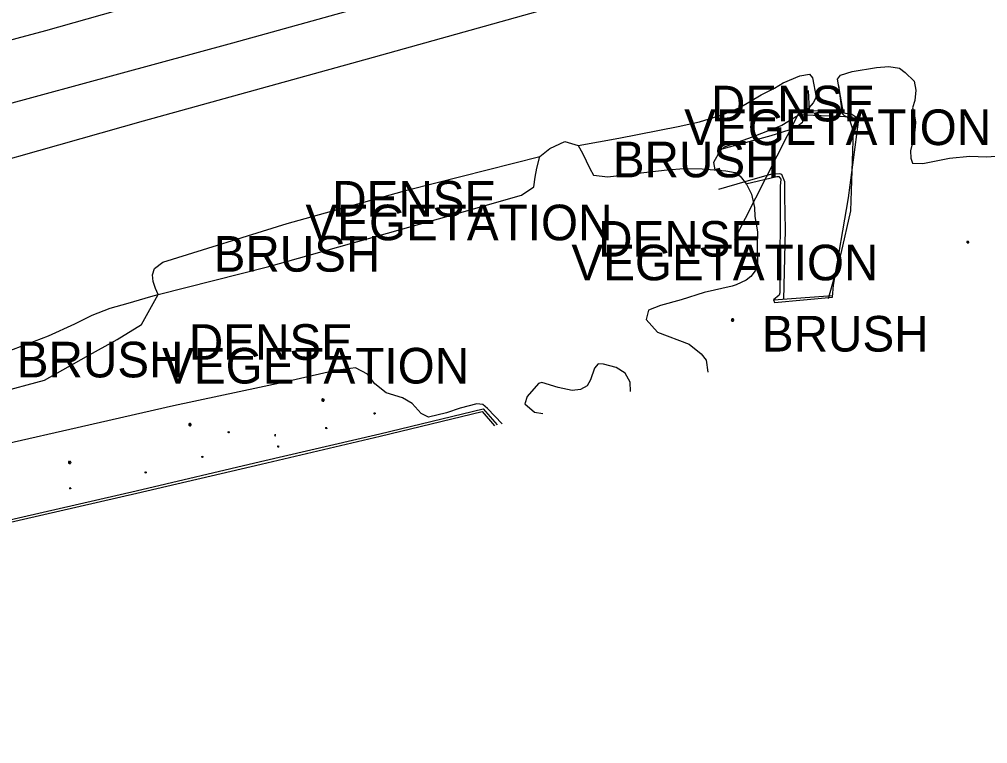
# Model space of a CAD drawing. Extents: x 2129547 to 2134906, y 657330 to 659734.
# Drawn here: x 2130043 to 2130233.3, y 657679.1 to 657821.5 of the extents above; entities that cross this region are included whole.
import ezdxf

# ---------------------------------------------------------------- set-up
doc = ezdxf.new("R2010")
doc.units = 0
for name, color, linetype in [('DR_X_Culvert', 7, 'Continuous'), ('HY_X_Water_Edge', 7, 'Continuous'), ('LT_X_Poles', 7, 'Continuous'), ('PM_X_Edge_Line', 7, 'Continuous'), ('PM_X_Lane_Line', 7, 'Continuous'), ('PV_X_Curb', 7, 'Continuous'), ('PV_X_EOP2', 7, 'Continuous'), ('PV_X_Parking_Lot', 7, 'Continuous'), ('PV_X_Shoulder', 7, 'Continuous'), ('RD_X_Fence', 7, 'Continuous'), ('VG_X_Cells', 7, 'Continuous'), ('VG_X_Shrub_Line_Lt', 7, 'Continuous'), ('VG_X_Text', 7, 'Continuous'), ('VG_X_Tree_Line_Lt', 7, 'Continuous')]:
    doc.layers.add(name, color=color, linetype=linetype)

msp = doc.modelspace()

# ---------------------------------------------------------------- linework, layer by layer
at = {"layer": 'DR_X_Culvert'}
msp.add_line((2130191.17, 657766.38), (2130202.8, 657767.25), dxfattribs=at)
msp.add_lwpolyline([(2130198.02, 657807.49), (2130198.19, 657803.6), (2130204.7, 657803.43), (2130204.05, 657808.51)], dxfattribs=at)
at = {"layer": 'HY_X_Water_Edge'}
for points in [[(2130180.35, 657795.88), (2130190.75, 657798.68), (2130194.27, 657799.78), (2130196.02, 657800.63), (2130196.88, 657801.31), (2130198.15, 657803.76)], [(2130204.37, 657803.54), (2130204.49, 657803.18), (2130205.09, 657802.63), (2130205.59, 657802.32), (2130206.19, 657801.59), (2130206.86, 657799.6), (2130206.34, 657783.85), (2130204.4, 657775.46), (2130201.93, 657766.58)], [(2130193.18, 657766.42), (2130193.54, 657780.13), (2130193.39, 657786.68), (2130193.44, 657789.55), (2130192.83, 657791.03), (2130192.4, 657791.16), (2130190.77, 657791.08), (2130185.55, 657789.56), (2130180.34, 657788.04)]]:
    msp.add_lwpolyline(points, dxfattribs=at)
at = {"layer": 'LT_X_Poles'}
msp.add_lwpolyline([(2130093.26, 657739.95), (2130093.18, 657739.65), (2130093.3, 657739.65)], dxfattribs=at)
msp.add_circle((2130093.22, 657739.8), 0.065, dxfattribs=at)
at = {"layer": 'PM_X_Edge_Line'}
msp.add_lwpolyline([(2129781.33, 657733.06), (2129822.4, 657744.28), (2129902.75, 657766.7), (2130016.9, 657798.42), (2130084.9, 657816.89), (2130135.24, 657830.94), (2130189.26, 657846.05), (2130240.42, 657859.85), (2130282.16, 657871.36), (2130318.23, 657881.32), (2130332.01, 657885.16), (2130356.78, 657892.02), (2130375.64, 657897.24), (2130413.2, 657907.59), (2130448.12, 657917.07), (2130481.79, 657926.44), (2130514.96, 657935.23), (2130533.56, 657939.51)], dxfattribs=at)
at = {"layer": 'PM_X_Lane_Line'}
msp.add_lwpolyline([(2130557.28, 657959.92), (2130518.18, 657949.28), (2130479.22, 657938.42), (2130439.87, 657927.68), (2130400.48, 657916.61), (2130360.47, 657905.46), (2130353.72, 657903.61), (2130321.86, 657894.87), (2130315.15, 657893.02), (2130282.49, 657883.85), (2130241.71, 657872.68), (2130201.93, 657862), (2130163.85, 657851.39), (2130126, 657840.99), (2130086.64, 657830.21), (2130048.06, 657819.28), (2130006.64, 657808.18), (2129969.33, 657798.07), (2129930.34, 657787.23), (2129890.21, 657775.75), (2129850.72, 657764.54), (2129813.2, 657754.11), (2129781.62, 657745.43)], dxfattribs=at)
at = {"layer": 'PV_X_Curb'}
msp.add_lwpolyline([(2129884.57, 657679.15), (2129883.01, 657681.79), (2129889.43, 657687), (2129928.6, 657696.31), (2129964.8, 657704.85), (2129999.37, 657713.02), (2130035.56, 657721.89), (2130065.94, 657728.85), (2130090.35, 657734.59), (2130113.79, 657740.05), (2130134.12, 657744.97), (2130136.89, 657741.78)], dxfattribs=at)
at = {"layer": 'PV_X_EOP2'}
msp.add_lwpolyline([(2129781.33, 657733.06), (2129822.4, 657744.28), (2129902.75, 657766.7), (2130016.9, 657798.42), (2130084.9, 657816.89), (2130135.24, 657830.94), (2130189.26, 657846.05), (2130240.42, 657859.85), (2130282.16, 657871.36), (2130318.23, 657881.32), (2130332.01, 657885.16), (2130356.78, 657892.02), (2130375.64, 657897.24), (2130413.2, 657907.59), (2130448.12, 657917.07), (2130481.79, 657926.44), (2130514.96, 657935.23), (2130533.56, 657939.51)], dxfattribs=at)
at = {"layer": 'PV_X_Parking_Lot'}
msp.add_lwpolyline([(2129885.07, 657679.28), (2129883.66, 657681.67), (2129889.66, 657686.54), (2129928.71, 657695.83), (2129964.91, 657704.36), (2129999.49, 657712.53), (2130035.68, 657721.4), (2130066.05, 657728.37), (2130090.47, 657734.1), (2130113.9, 657739.56), (2130133.94, 657744.42), (2130136.35, 657741.64)], dxfattribs=at)
at = {"layer": 'PV_X_Shoulder'}
msp.add_lwpolyline([(2129781.12, 657723.15), (2129791.26, 657725.96), (2129847.2, 657740.42), (2129910.54, 657757.22), (2129956.62, 657769.85), (2130017.82, 657787.52), (2130067.36, 657801.54), (2130112.53, 657814.1), (2130168.41, 657829.75), (2130217.23, 657843.2), (2130272.91, 657858.21), (2130320.81, 657871.55), (2130356.56, 657881.59), (2130359.33, 657882.35), (2130366.22, 657884.23)], dxfattribs=at)
at = {"layer": 'RD_X_Fence'}
msp.add_lwpolyline([(2130206.71, 657802.26), (2130195.95, 657802.72), (2130183.51, 657778.21)], dxfattribs=at)
at = {"layer": 'VG_X_Cells'}
for p, q in [((2130229.12, 657777.73), (2130229.37, 657777.73)), ((2130229.37, 657777.73), (2130229.15, 657777.79)), ((2130229.37, 657777.73), (2130229.15, 657777.65)), ((2130229.37, 657777.73), (2130229.17, 657777.85)), ((2130229.37, 657777.73), (2130229.17, 657777.62)), ((2130229.37, 657777.73), (2130229.17, 657777.58)), ((2130229.37, 657777.73), (2130229.19, 657777.91)), ((2130229.37, 657777.73), (2130229.22, 657777.56)), ((2130229.37, 657777.73), (2130229.25, 657777.53)), ((2130229.37, 657777.73), (2130229.29, 657777.52)), ((2130229.37, 657777.73), (2130229.31, 657777.96)), ((2130229.37, 657777.73), (2130229.31, 657777.49)), ((2130229.37, 657777.73), (2130229.34, 657777.5)), ((2130229.37, 657777.73), (2130229.43, 657777.97)), ((2130229.37, 657777.73), (2130229.5, 657777.93)), ((2130229.37, 657777.73), (2130229.55, 657777.87)), ((2130229.37, 657777.73), (2130229.61, 657777.81)), ((2130229.37, 657777.73), (2130229.59, 657777.74)), ((2130229.37, 657777.47), (2130229.37, 657777.73)), ((2130229.37, 657777.73), (2130229.42, 657777.5)), ((2130229.37, 657777.73), (2130229.47, 657777.5)), ((2130229.37, 657777.73), (2130229.5, 657777.54)), ((2130229.37, 657777.73), (2130229.55, 657777.56)), ((2130229.37, 657777.73), (2130229.56, 657777.61)), ((2130229.37, 657777.73), (2130229.59, 657777.64)), ((2130229.37, 657777.73), (2130229.61, 657777.69))]:
    msp.add_line(p, q, dxfattribs=at)
for points in [[(2130112.79, 657744.15), (2130112.82, 657744.19), (2130112.84, 657744.13), (2130112.9, 657744.14), (2130112.88, 657744.09), (2130112.93, 657744.06), (2130112.89, 657744.03), (2130112.9, 657743.98), (2130112.86, 657743.98), (2130112.84, 657743.94), (2130112.82, 657743.97), (2130112.79, 657743.93), (2130112.77, 657743.98), (2130112.72, 657743.96), (2130112.73, 657744), (2130112.69, 657744), (2130112.71, 657744.04), (2130112.67, 657744.07), (2130112.71, 657744.08), (2130112.68, 657744.12), (2130112.72, 657744.11), (2130112.72, 657744.17), (2130112.76, 657744.14), (2130112.77, 657744.19), (2130112.79, 657744.15)], [(2130103.27, 657741.26), (2130103.3, 657741.3), (2130103.32, 657741.25), (2130103.37, 657741.26), (2130103.35, 657741.21), (2130103.4, 657741.18), (2130103.36, 657741.14), (2130103.37, 657741.09), (2130103.33, 657741.1), (2130103.32, 657741.05), (2130103.3, 657741.09), (2130103.26, 657741.05), (2130103.24, 657741.09), (2130103.19, 657741.07), (2130103.2, 657741.12), (2130103.16, 657741.11), (2130103.18, 657741.15), (2130103.14, 657741.18), (2130103.18, 657741.19), (2130103.15, 657741.23), (2130103.2, 657741.23), (2130103.2, 657741.28), (2130103.23, 657741.25), (2130103.24, 657741.3), (2130103.27, 657741.26)], [(2130084.1, 657740.45), (2130084.13, 657740.49), (2130084.15, 657740.43), (2130084.2, 657740.44), (2130084.19, 657740.39), (2130084.23, 657740.36), (2130084.19, 657740.33), (2130084.2, 657740.28), (2130084.17, 657740.28), (2130084.15, 657740.24), (2130084.13, 657740.27), (2130084.09, 657740.23), (2130084.07, 657740.28), (2130084.02, 657740.25), (2130084.03, 657740.3), (2130083.99, 657740.3), (2130084.01, 657740.34), (2130083.98, 657740.37), (2130084.01, 657740.38), (2130083.98, 657740.42), (2130084.03, 657740.41), (2130084.03, 657740.46), (2130084.07, 657740.44), (2130084.08, 657740.49), (2130084.1, 657740.45)], [(2130093.83, 657737.63), (2130093.86, 657737.67), (2130093.88, 657737.62), (2130093.93, 657737.63), (2130093.92, 657737.58), (2130093.96, 657737.55), (2130093.92, 657737.51), (2130093.93, 657737.46), (2130093.9, 657737.47), (2130093.88, 657737.42), (2130093.86, 657737.46), (2130093.82, 657737.42), (2130093.8, 657737.46), (2130093.75, 657737.44), (2130093.76, 657737.49), (2130093.72, 657737.48), (2130093.74, 657737.52), (2130093.71, 657737.55), (2130093.74, 657737.56), (2130093.71, 657737.6), (2130093.76, 657737.6), (2130093.76, 657737.65), (2130093.79, 657737.62), (2130093.81, 657737.67), (2130093.83, 657737.63)], [(2130078.93, 657735.61), (2130078.96, 657735.65), (2130078.98, 657735.6), (2130079.03, 657735.61), (2130079.01, 657735.56), (2130079.06, 657735.53), (2130079.02, 657735.49), (2130079.03, 657735.44), (2130078.99, 657735.45), (2130078.98, 657735.4), (2130078.96, 657735.44), (2130078.92, 657735.39), (2130078.9, 657735.44), (2130078.85, 657735.42), (2130078.86, 657735.46), (2130078.82, 657735.46), (2130078.84, 657735.5), (2130078.8, 657735.53), (2130078.84, 657735.54), (2130078.81, 657735.58), (2130078.86, 657735.58), (2130078.86, 657735.63), (2130078.89, 657735.6), (2130078.9, 657735.65), (2130078.93, 657735.61)], [(2130067.76, 657732.54), (2130067.79, 657732.58), (2130067.81, 657732.53), (2130067.87, 657732.54), (2130067.85, 657732.49), (2130067.9, 657732.46), (2130067.85, 657732.42), (2130067.87, 657732.37), (2130067.83, 657732.38), (2130067.81, 657732.33), (2130067.79, 657732.37), (2130067.76, 657732.33), (2130067.74, 657732.37), (2130067.68, 657732.35), (2130067.69, 657732.4), (2130067.65, 657732.39), (2130067.68, 657732.43), (2130067.64, 657732.46), (2130067.68, 657732.47), (2130067.65, 657732.51), (2130067.69, 657732.51), (2130067.69, 657732.56), (2130067.73, 657732.53), (2130067.74, 657732.58), (2130067.76, 657732.54)], [(2130052.94, 657729.43), (2130052.97, 657729.47), (2130052.99, 657729.42), (2130053.05, 657729.42), (2130053.03, 657729.37), (2130053.08, 657729.34), (2130053.04, 657729.31), (2130053.05, 657729.26), (2130053.01, 657729.27), (2130052.99, 657729.22), (2130052.97, 657729.25), (2130052.94, 657729.21), (2130052.92, 657729.26), (2130052.87, 657729.24), (2130052.88, 657729.28), (2130052.84, 657729.28), (2130052.86, 657729.32), (2130052.82, 657729.35), (2130052.86, 657729.36), (2130052.83, 657729.4), (2130052.87, 657729.39), (2130052.87, 657729.45), (2130052.91, 657729.42), (2130052.92, 657729.47), (2130052.94, 657729.43)]]:
    msp.add_lwpolyline(points, dxfattribs=at)
for centre, radius in [((2130183.13, 657762.41), 0.012), ((2130102.64, 657746.68), 0.012), ((2130112.8, 657744.06), 0.0115), ((2130076.48, 657741.85), 0.012), ((2130103.27, 657741.17), 0.0115), ((2130084.1, 657740.36), 0.0115), ((2130093.83, 657737.54), 0.0115), ((2130078.93, 657735.52), 0.0115), ((2130052.84, 657734.41), 0.012), ((2130067.76, 657732.45), 0.0115), ((2130052.95, 657729.34), 0.0115)]:
    msp.add_circle(centre, radius, dxfattribs=at)
for centre, radius, start, end in [((2130182.97, 657762.5), 0.0735, 39.0625, 279.5412), ((2130182.99, 657762.33), 0.0987, 96.1722, 320.5737), ((2130183.08, 657762.58), 0.0658, 354.0047, 205.9741), ((2130183.18, 657762.28), 0.114, 184.9476, 19.4572), ((2130183.22, 657762.55), 0.0776, 323.83, 165.0376), ((2130183.31, 657762.41), 0.0957, 259.1453, 101.4596), ((2130102.47, 657746.78), 0.0735, 39.0625, 279.5412), ((2130102.59, 657746.85), 0.0658, 354.0047, 205.9741), ((2130102.73, 657746.82), 0.0776, 323.83, 165.0376), ((2130102.5, 657746.6), 0.0987, 96.1722, 320.5737), ((2130102.69, 657746.55), 0.114, 184.9476, 19.4572), ((2130102.81, 657746.68), 0.0957, 259.1453, 101.4596), ((2130076.31, 657741.94), 0.0735, 39.0625, 279.5412), ((2130076.34, 657741.77), 0.0987, 96.1722, 320.5737), ((2130076.43, 657742.02), 0.0658, 354.0047, 205.9741), ((2130076.53, 657741.72), 0.114, 184.9476, 19.4572), ((2130076.57, 657741.99), 0.0776, 323.83, 165.0376), ((2130076.65, 657741.85), 0.0957, 259.1453, 101.4596), ((2130052.67, 657734.51), 0.0735, 39.0625, 279.5412), ((2130052.7, 657734.34), 0.0987, 96.1722, 320.5737), ((2130052.79, 657734.58), 0.0658, 354.0047, 205.9741), ((2130052.89, 657734.28), 0.114, 184.9476, 19.4572), ((2130052.93, 657734.56), 0.0776, 323.83, 165.0376), ((2130053.01, 657734.42), 0.0957, 259.1453, 101.4596)]:
    msp.add_arc(centre, radius, start, end, dxfattribs=at)
at = {"layer": 'VG_X_Shrub_Line_Lt'}
for points in [[(2130185.74, 657789.15), (2130191.85, 657790.64), (2130192.26, 657790.61), (2130192.59, 657790.1), (2130192.48, 657788.73), (2130192.4, 657767.78), (2130192.29, 657767.28), (2130191.17, 657766.38), (2130191.38, 657765.86), (2130202.77, 657766.9), (2130202.95, 657769.29), (2130205.9, 657786.4), (2130207.9, 657801.39), (2130207.35, 657802.27), (2130206.58, 657802.83), (2130204.92, 657803.07), (2130203.76, 657809.73), (2130204.37, 657810.54), (2130206.62, 657811.24), (2130211.41, 657812.03), (2130213.85, 657812.25), (2130215.92, 657811.94), (2130217.09, 657811.09), (2130218.83, 657809.34), (2130219.17, 657807.6), (2130218.98, 657805.58), (2130218.51, 657804.12), (2130218.74, 657803.4), (2130219.09, 657801.3), (2130218.97, 657799.63), (2130218.39, 657796.77), (2130218.09, 657795.63), (2130218.15, 657794.23), (2130218.47, 657793.24), (2130220.55, 657793.17), (2130225.78, 657794.19), (2130229.77, 657794.6), (2130233.02, 657794.45), (2130237.59, 657794.84)], [(2130152.76, 657796.71), (2130160.8, 657798.14), (2130172.44, 657800.44), (2130176.65, 657801.37), (2130181.12, 657802.75), (2130184.56, 657804.21), (2130188.75, 657806.64), (2130191.41, 657807.97), (2130193.09, 657809), (2130196.34, 657810.42), (2130198.26, 657810.73), (2130198.82, 657810.04), (2130199.54, 657806.22), (2130198.97, 657805.07), (2130197.73, 657803.66), (2130192.83, 657800.62), (2130187.02, 657798.37), (2130181.47, 657796.35), (2130180.63, 657795.57), (2130179.36, 657793.38), (2130179.68, 657791.9)], [(2130018.81, 657750.13), (2130032.49, 657753.79), (2130040.43, 657756.16), (2130048.7, 657759.33), (2130053.87, 657761.67), (2130057.28, 657763.33), (2130060.77, 657764.71), (2130064.36, 657765.7), (2130068.81, 657767.04), (2130070.22, 657767.4), (2130069.69, 657768.63), (2130069.28, 657770.01), (2130069.12, 657771.32), (2130069.49, 657772.54), (2130071.16, 657773.8), (2130095.59, 657781.36), (2130119.35, 657787.99), (2130145.24, 657794.52)]]:
    msp.add_lwpolyline(points, dxfattribs=at)
at = {"layer": 'VG_X_Tree_Line_Lt'}
for points in [[(2130038.56, 657748.08), (2130047.9, 657750.58), (2130056.18, 657755.26), (2130062.18, 657758.57), (2130066.94, 657761.53), (2130070.22, 657767.4), (2130092.02, 657772.95), (2130125.34, 657782.28), (2130141.67, 657786.92), (2130144.06, 657788.57), (2130144.32, 657790.48), (2130144.64, 657792.26), (2130145.24, 657794.52), (2130147.2, 657796.11), (2130150.17, 657797.52), (2130152.76, 657796.71), (2130153.65, 657795.19), (2130155.07, 657792.21), (2130155.8, 657790.91), (2130158.59, 657790.54), (2130164.55, 657791.28), (2130170.26, 657791.92), (2130173.61, 657792.17), (2130177.13, 657792.14), (2130181.79, 657791.7), (2130183.62, 657791.4), (2130184.61, 657790.68), (2130185.89, 657789.14), (2130186.88, 657787.14), (2130187.44, 657784.5), (2130187.54, 657782.76), (2130188.04, 657779.75), (2130187.98, 657776.97), (2130188.02, 657773.31), (2130187.57, 657772.1), (2130186.75, 657770.97), (2130185.81, 657770.22), (2130183.85, 657769.3), (2130183.06, 657769.06), (2130177.55, 657767.82), (2130173.03, 657766.38), (2130168.94, 657765.23), (2130166.61, 657764.34), (2130166.16, 657762.52), (2130168.39, 657760.02), (2130174.63, 657757.63), (2130176.99, 657755.75), (2130177.95, 657754.54), (2130178.3, 657752.19)], [(2130137.84, 657742.02), (2130134.94, 657745), (2130134.06, 657745.81), (2130132.87, 657745.92), (2130129.58, 657745.09), (2130126.91, 657744.18), (2130123.36, 657743.33), (2130121.92, 657744.04), (2130120.17, 657746.03), (2130118.23, 657747.12), (2130115.03, 657748.07), (2130112.8, 657749.89), (2130111.38, 657751.77), (2130109, 657753.01), (2130105.12, 657752.48), (2130095.09, 657750.22), (2130073.23, 657745.53), (2130052.89, 657740.89), (2130030.94, 657735.91)], [(2130163.09, 657748.36), (2130162.98, 657750.16), (2130162.04, 657751.95), (2130160.27, 657753.06), (2130157.74, 657753.73), (2130156.7, 657753.77), (2130156.03, 657752.94), (2130155.21, 657750.65), (2130154.53, 657749.49), (2130153.23, 657748.78), (2130151.58, 657748.56), (2130148.88, 657749.12), (2130145.67, 657750.1), (2130144.99, 657749.93), (2130142.77, 657747.36), (2130142.29, 657745.94), (2130144.23, 657744.32), (2130145.82, 657744.02)]]:
    msp.add_lwpolyline(points, dxfattribs=at)

# ---------------------------------------------------------------- texts
at = {"layer": 'VG_X_Text'}
for s, p in [('DENSE', (2130178.89, 657801.45)), ('VEGETATION', (2130173.63, 657796.79)), ('BRUSH', (2130159.6, 657790.46)), ('DENSE', (2130104.44, 657782.74)), ('VEGETATION', (2130099.19, 657778.08)), ('DENSE', (2130156.71, 657774.86)), ('BRUSH', (2130081.14, 657771.91)), ('VEGETATION', (2130151.46, 657770.21)), ('BRUSH', (2130188.9, 657756.21)), ('DENSE', (2130076.27, 657754.59)), ('BRUSH', (2130042.44, 657751.13)), ('VEGETATION', (2130071.01, 657749.93))]:
    msp.add_text(s, height=7, dxfattribs=at).set_placement(p)

doc.saveas('drawing.dxf')
